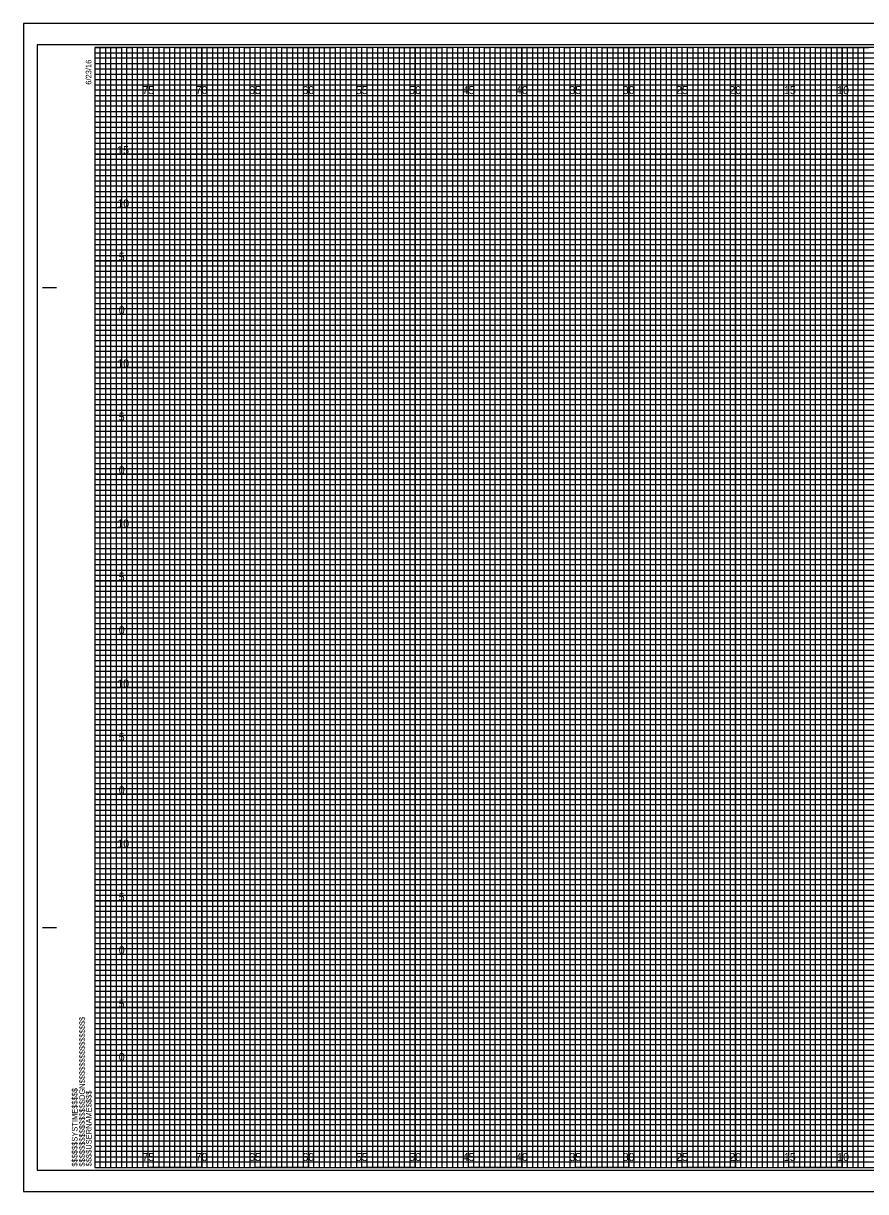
# Model space of a CAD drawing. Extents: x -7 to 162, y -2 to 107.
# Drawn here: x -6.7 to 72.2, y -2.3 to 107.3 of the extents above; entities that cross this region are included whole.
import ezdxf

# ---------------------------------------------------------------- set-up
doc = ezdxf.new("R2010")
doc.units = 0
for name, color, linetype in [('Prop XS Elevation Labels', 7, 'Continuous'), ('Prop XS Offset Labels', 7, 'Continuous'), ('Sheet Cross Section CELL', 7, 'Continuous'), ('Sheet Cross Section Grid Major CELL', 7, 'Continuous'), ('Sheet Cross Section Grid Middle CELL', 7, 'Continuous'), ('Sheet Cross Section Grid Minor 1 CELL', 7, 'Continuous'), ('Sheet Cross Section Grid Minor 2 CELL', 7, 'Continuous'), ('Sheet Cutting Line CELL', 7, 'Continuous'), ('Sheet DOT Grid CELL', 7, 'Continuous'), ('Sheet Plot Border Inside CELL', 7, 'Continuous'), ('Sheet Plot Border Outside CELL', 7, 'Continuous')]:
    doc.layers.add(name, color=color, linetype=linetype)

msp = doc.modelspace()

# ---------------------------------------------------------------- linework, layer by layer
at = {"layer": 'Sheet Cross Section CELL'}
for p, q in [((-4.9, 82.5), (-3.65, 82.5)), ((-4.85, 82.5), (-3.6, 82.5)), ((-4.9, 22.5), (-3.65, 22.5)), ((-4.85, 22.5), (-3.6, 22.5)), ((0, 0), (0, 0)), ((0, 0), (0, 0)), ((0, 0), (0, 0)), ((0, 0), (0, 0)), ((0, 0), (0, 0)), ((0, 0), (0, 0)), ((0, 0), (0, 0))]:
    msp.add_line(p, q, dxfattribs=at)
msp.add_lwpolyline([(160, 105), (0, 105), (0, 0), (160, 0)], close=True, dxfattribs=at)
at = {"layer": 'Sheet Cross Section Grid Major CELL'}
for p, q in [((5, 105), (0, 105)), ((5, 0), (5, 105)), ((15, 105), (10, 105)), ((10, 105), (10, 0)), ((15, 0), (15, 105)), ((25, 105), (20, 105)), ((20, 105), (20, 0)), ((25, 0), (25, 105)), ((35, 105), (30, 105)), ((30, 105), (30, 0)), ((35, 0), (35, 105)), ((45, 105), (40, 105)), ((40, 105), (40, 0)), ((45, 0), (45, 105)), ((55, 105), (50, 105)), ((50, 105), (50, 0)), ((55, 0), (55, 105)), ((65, 105), (60, 105)), ((60, 105), (60, 0)), ((65, 0), (65, 105)), ((75, 105), (70, 105)), ((70, 105), (70, 0)), ((10, 0), (5, 0)), ((20, 0), (15, 0)), ((30, 0), (25, 0)), ((40, 0), (35, 0)), ((50, 0), (45, 0)), ((60, 0), (55, 0)), ((70, 0), (65, 0))]:
    msp.add_line(p, q, dxfattribs=at)
for points in [[(0, 100), (160, 100), (160, 95), (0, 95)], [(0, 90), (160, 90), (160, 85), (0, 85)], [(0, 80), (160, 80), (160, 75), (0, 75)], [(0, 70), (160, 70), (160, 65), (0, 65)], [(0, 60), (160, 60), (160, 55), (0, 55)], [(0, 50), (160, 50), (160, 45), (0, 45)], [(0, 40), (160, 40), (160, 35), (0, 35)], [(0, 30), (160, 30), (160, 25), (0, 25)], [(0, 20), (160, 20), (160, 15), (0, 15)], [(0, 10), (160, 10), (160, 5), (0, 5)]]:
    msp.add_lwpolyline(points, dxfattribs=at)
at = {"layer": 'Sheet Cross Section Grid Middle CELL'}
for points in [[(0, 105), (2.5, 105), (2.5, 0), (7.5, 0), (7.5, 105), (12.5, 105), (12.5, 0), (17.5, 0), (17.5, 105), (22.5, 105), (22.5, 0), (27.5, 0), (27.5, 105), (32.5, 105), (32.5, 0), (37.5, 0), (37.5, 105), (42.5, 105), (42.5, 0), (47.5, 0), (47.5, 105), (52.5, 105), (52.5, 0), (57.5, 0), (57.5, 105), (62.5, 105), (62.5, 0), (67.5, 0), (67.5, 105), (72.5, 105)], [(0, 102.5), (137.5, 102.5)], [(0, 92.5), (160, 92.5), (160, 97.5), (0, 97.5)], [(0, 82.5), (160, 82.5), (160, 87.5), (0, 87.5)], [(0, 72.5), (160, 72.5), (160, 77.5), (0, 77.5)], [(0, 62.5), (160, 62.5), (160, 67.5), (0, 67.5)], [(0, 52.5), (160, 52.5), (160, 57.5), (0, 57.5)], [(0, 42.5), (160, 42.5), (160, 47.5), (0, 47.5)], [(0, 32.5), (160, 32.5), (160, 37.5), (0, 37.5)], [(0, 22.5), (160, 22.5), (160, 27.5), (0, 27.5)], [(0, 12.5), (160, 12.5), (160, 17.5), (0, 17.5)], [(0, 2.5), (160, 2.5), (160, 7.5), (0, 7.5)]]:
    msp.add_lwpolyline(points, dxfattribs=at)
at = {"layer": 'Sheet Cross Section Grid Minor 1 CELL'}
for p, q in [((0, 104.5), (130, 104.5)), ((130, 103.99), (0, 103.99)), ((0, 103.99), (0, 103.5)), ((0, 103.5), (130, 103.5)), ((130, 102.95), (0, 102.95)), ((0, 102.95), (0, 102)), ((0, 102), (160, 102))]:
    msp.add_line(p, q, dxfattribs=at)
for points in [[(0, 101.5), (135, 101.5), (160, 101.5), (160, 101), (0, 101)], [(0, 100.5), (160, 100.5), (160, 99.5), (0, 99.5)], [(0, 99), (160, 99), (160, 98.5), (0, 98.49)], [(0, 98), (160, 98), (160, 97), (0, 97)], [(0, 96.5), (160, 96.5), (160, 96), (0, 96)], [(0, 95.5), (160, 95.5), (160, 94.5), (0, 94.5)], [(0, 94), (160, 94), (160, 93.5), (0, 93.5)], [(0, 93), (160, 93), (160, 92), (0, 92)], [(0, 91.5), (160, 91.5), (160, 91), (0, 91)], [(0, 90.5), (160, 90.5), (160, 89.5), (0, 89.5)], [(0, 89), (160, 89), (160, 88.5), (0, 88.5)], [(0, 88), (160, 88), (160, 86.98), (160, 86.5), (160, 86), (0, 86)], [(0, 87), (160, 87), (160, 86.5), (0, 86.5)], [(0, 85.5), (160, 85.5), (160, 84.5), (0, 84.52)], [(0, 84.52), (160, 84.5), (160, 84), (0, 84)], [(0, 83.5), (160, 83.5), (160, 83), (0, 83)], [(0, 82), (160, 82), (160, 81.5), (0, 81.5)], [(0, 81), (160, 81), (160, 80.5), (0, 80.5)], [(-0.04, 79.45), (160, 79.45), (160, 78.94), (-0.04, 78.94)], [(0, 78.5), (160, 78.5), (160, 78), (0, 78)], [(0, 77), (160, 77), (160, 76.5), (0, 76.5)], [(0, 76), (160, 76), (160, 75.5), (0, 75.5)], [(0, 74.5), (160, 74.5), (160, 74), (0, 74)], [(0, 73.5), (160, 73.5), (160, 73), (0, 73)], [(0, 72), (160, 72), (160, 71.5), (0, 71.5)], [(0, 71), (160, 71), (160, 70.5), (0, 70.5)], [(0, 69.5), (160, 69.5), (160, 68.99), (0, 69)], [(0, 68.5), (160, 68.5), (160, 68), (0, 68)], [(0, 67), (160, 67), (160, 66.5), (0, 66.5)], [(0, 66), (160, 66), (160, 65.5), (0, 65.5)], [(0, 64.5), (160, 64.5), (160, 64), (0, 64)], [(0, 63.5), (160, 63.5), (160, 63), (0, 63)], [(0, 62), (160, 62), (160, 61.5), (0, 61.5)], [(0, 61), (160, 61), (160, 60.5), (0, 60.5)], [(0, 59.5), (160, 59.5), (160, 59), (0, 59)], [(0, 58.5), (160.03, 58.45), (160, 58), (0, 58)], [(0, 57), (160, 57), (160, 56.5), (0, 56.5)], [(0, 56), (160, 56), (160, 55.5), (0, 55.5)], [(0, 54.5), (160, 54.5), (160, 54), (0, 54)], [(0, 53.5), (160, 53.5), (160, 53), (0, 53)], [(0, 52), (160, 52), (160, 51.5), (0, 51.5)], [(0, 51), (160, 51), (160, 50.5), (0, 50.5)], [(0, 49.5), (160, 49.5), (160, 49), (0, 49)], [(0, 48.5), (160, 48.5), (160, 48), (0, 48)], [(0, 47), (160, 47), (160, 46.5), (0, 46.5)], [(0, 46), (160, 46), (160, 45.5), (0, 45.5)], [(0, 44.5), (160, 44.5), (160, 44), (0, 44)], [(0, 43.5), (160, 43.5), (160, 43), (0, 43)], [(0, 42), (160, 42), (160, 41.5), (0, 41.5)], [(0, 41), (160, 41), (160, 40.5), (0, 40.5)], [(0, 39.5), (160, 39.5), (160, 38.99), (0, 39)], [(0, 38.5), (160, 38.5), (160, 38), (0, 38)], [(0, 37), (160, 37), (160, 36.5), (0, 36.5)], [(0, 36), (160, 36), (160, 35.5), (0, 35.5)], [(0, 34.5), (160, 34.5), (160, 34), (0, 34)], [(0, 33.5), (160, 33.5), (160, 33), (0, 33)], [(0, 32), (160, 32), (160, 31.5), (0, 31.5)], [(0, 31), (160, 31), (160, 30.5), (0, 30.5)], [(0, 29.5), (160, 29.5), (160, 29), (0, 29)], [(0, 28.5), (160.03, 28.46), (160, 28), (0, 28)], [(0, 27), (160, 27), (160, 26.5), (0, 26.5)], [(0, 26), (160, 26), (160, 25.5), (0, 25.5)], [(0, 24.5), (160, 24.5), (160, 24), (0, 24)], [(0, 23.5), (160, 23.5), (160, 23), (0, 23)], [(0, 22), (160, 22), (160, 21.5), (0, 21.5)], [(0, 21), (160, 21), (160, 20.5), (0, 20.5)], [(0, 19.5), (160, 19.5), (160, 19), (0, 19)], [(0, 18.5), (160, 18.5), (160, 18), (0, 18)], [(0, 17), (160, 17), (160, 16.5), (0, 16.5)], [(0, 16), (160, 16), (160, 15.5), (0, 15.5)], [(0, 14.5), (160, 14.5), (160, 14), (0, 14)], [(0, 13.5), (160, 13.5), (160, 13), (0, 13)], [(0, 12), (160, 12), (160, 11.5), (0, 11.5)], [(0, 11), (160, 11), (160, 10.5), (0, 10.5)], [(0, 9.5), (160, 9.5), (160, 9), (0, 9)], [(0, 8.5), (160, 8.5), (160, 8), (0, 8)], [(0, 7), (160, 7), (160, 6.5), (0, 6.5)], [(0, 6), (160, 6), (160, 5.5), (0, 5.5)], [(0, 4.5), (160, 4.5), (160, 4), (0, 4)], [(0, 3.5), (160, 3.5), (160, 3), (0, 3)], [(0, 2), (160, 2), (160, 1.5), (0, 1.5)], [(0, 1), (160, 1), (160, 0.5), (0, 0.5)]]:
    msp.add_lwpolyline(points, dxfattribs=at)
at = {"layer": 'Sheet Cross Section Grid Minor 2 CELL'}
for points in [[(0, 0), (0.5, 0), (0.5, 105), (1, 105), (1, 0)], [(1, 0), (1.5, 0), (1.5, 105), (2, 105), (2, 0)], [(2.5, 0), (3, 0), (3, 105), (3.5, 105), (3.5, 0)], [(3.5, 0), (4, 0), (4, 105), (4.5, 105), (4.5, 0)], [(5, 0), (5.5, 0), (5.5, 105), (6, 105), (6, 0)], [(6, 0), (6.5, 0), (6.5, 105), (7, 105), (7, 0)], [(7.5, 0), (8, 0), (8, 105), (8.5, 105), (8.5, 0)], [(8.5, 0), (9, 0), (9, 105), (9.5, 105), (9.5, 0)], [(10, 0), (10.5, 0), (10.5, 105), (11, 105), (11, 0)], [(11, 0), (11.5, 0), (11.5, 105), (12, 105), (12, 0)], [(12.5, 0), (13, 0), (13, 105), (13.5, 105), (13.5, 0)], [(13.5, 0), (14, 0), (14, 105), (14.5, 105), (14.5, 0)], [(15, 0), (15.5, 0), (15.5, 105), (16, 105), (16, 0)], [(16, 0), (16.5, 0), (16.5, 105), (17, 105), (17, 0)], [(17.5, 0), (18, 0), (18, 105), (18.5, 105), (18.5, 0)], [(18.5, 0), (19, 0), (19, 105), (19.5, 105), (19.5, 0)], [(20, 0), (20.5, 0), (20.5, 105), (21, 105), (21, 0)], [(21, 0), (21.5, 0), (21.5, 105), (22, 105), (22, 0)], [(22.5, 0), (23, 0), (23, 105), (23.5, 105), (23.5, 0)], [(23.5, 0), (24, 0), (24, 105), (24.5, 105), (24.5, 0)], [(25, 0), (25.5, 0), (25.5, 105), (26, 105), (26, 0)], [(26, 0), (26.5, 0), (26.5, 105), (27, 105), (27, 0)], [(27.5, 0), (28, 0), (28, 105), (28.5, 105), (28.5, 0)], [(28.5, 0), (29, 0), (29, 105), (29.5, 105), (29.5, 0)], [(30, 0), (30.5, 0), (30.5, 105), (31, 105), (31, 0)], [(31, 0), (31.5, 0), (31.5, 105), (32, 105), (32, 0)], [(32.5, 0), (33, 0), (33, 105), (33.5, 105), (33.5, 0)], [(33.5, 0), (34, 0), (34, 105), (34.5, 105), (34.5, 0)], [(35, 0), (35.5, 0), (35.5, 105), (36, 105), (36, 0)], [(36, 0), (36.5, 0), (36.5, 105), (37, 105), (37, 0)], [(37.5, 0), (38, 0), (38, 105), (38.5, 105), (38.5, 0)], [(38.5, 0), (39, 0), (39, 105), (39.5, 105), (39.5, 0)], [(40, 0), (40.5, 0), (40.5, 105), (41, 105), (41, 0)], [(41, 0), (41.5, 0), (41.5, 105), (42, 105), (42, 0)], [(42.5, 0), (43, 0), (43, 105), (43.5, 105), (43.5, 0)], [(43.5, 0), (44, 0), (44, 105), (44.5, 105), (44.5, 0)], [(45, 0), (45.5, 0), (45.5, 105), (46, 105), (46, 0)], [(46, 0), (46.5, 0), (46.5, 105), (47, 105), (47, 0)], [(47.5, 0), (48, 0), (48, 105), (48.5, 105), (48.5, 0)], [(48.5, 0), (49, 0), (49, 105), (49.5, 105), (49.5, 0)], [(50, 0), (50.5, 0), (50.5, 105), (51, 105), (51, 0)], [(51, 0), (51.5, 0), (51.5, 105), (52, 105), (52, 0)], [(52.5, 0), (53, 0), (53, 105), (53.5, 105), (53.5, 0)], [(53.5, 0), (54, 0), (54, 105), (54.5, 105), (54.5, 0)], [(55, 0), (55.5, 0), (55.5, 105), (56, 105), (56, 0)], [(56, 0), (56.5, 0), (56.5, 105), (57, 105), (57, 0)], [(57.5, 0), (58, 0), (58, 105), (58.5, 105), (58.5, 0)], [(58.5, 0), (59, 0), (59, 105), (59.5, 105), (59.5, 0)], [(60, 0), (60.5, 0), (60.5, 105), (61, 105), (61, 0)], [(61, 0), (61.5, 0), (61.5, 105), (62, 105), (62, 0)], [(62.5, 0), (63, 0), (63, 105), (63.5, 105), (63.5, 0)], [(63.5, 0), (64, 0), (64, 105), (64.5, 105), (64.5, 0)], [(65, 0), (65.5, 0), (65.5, 105), (66, 105), (66, 0)], [(66, 0), (66.5, 0), (66.5, 105), (67, 105), (67, 0)], [(67.5, 0), (68, 0), (68, 105), (68.5, 105), (68.5, 0)], [(68.5, 0), (69, 0), (69, 105), (69.5, 105), (69.5, 0)], [(70, 0), (70.5, 0), (70.5, 105), (71, 105), (71, 0)], [(71, 0), (71.5, 0), (71.5, 105), (72, 105), (72, 0)]]:
    msp.add_lwpolyline(points, dxfattribs=at)
at = {"layer": 'Sheet Cutting Line CELL'}
for p, q in [((161.65, 107.25), (-6.7, 107.25)), ((-6.7, 107.25), (-6.7, -2.25)), ((-6.7, -2.25), (161.65, -2.25))]:
    msp.add_line(p, q, dxfattribs=at)
at = {"layer": 'Sheet DOT Grid CELL'}
for p, q in [((5, 0), (5, 105)), ((10, 0), (10, 105)), ((15, 0), (15, 105)), ((20, 0), (20, 105)), ((25, 0), (25, 105)), ((30, 0), (30, 105)), ((35, 0), (35, 105)), ((40, 0), (40, 105)), ((45, 0), (45, 105)), ((50, 0), (50, 105)), ((55, 0), (55, 105)), ((60, 0), (60, 105)), ((65, 0), (65, 105)), ((70, 0), (70, 105)), ((0, 100), (160, 100)), ((0, 95), (160, 95)), ((0, 90), (160, 90)), ((0, 85), (160, 85)), ((0, 80), (160, 80)), ((0, 75), (160, 75)), ((0, 70), (160, 70)), ((0, 65), (160, 65)), ((0, 60), (160, 60)), ((0, 55), (160, 55)), ((0, 50), (160, 50)), ((0, 45), (160, 45)), ((0, 40), (160, 40)), ((0, 35), (160, 35)), ((0, 30), (160, 30)), ((0, 25), (160, 25)), ((0, 20), (160, 20)), ((0, 15), (160, 15)), ((0, 10), (160, 10)), ((0, 5), (160, 5))]:
    msp.add_line(p, q, dxfattribs=at)
at = {"layer": 'Sheet Plot Border Inside CELL'}
msp.add_lwpolyline([(-5.4, -0.25), (161.2, -0.25), (161.2, 105.25), (-5.4, 105.25)], close=True, dxfattribs=at)
at = {"layer": 'Sheet Plot Border Outside CELL'}
msp.add_lwpolyline([(-6.7, -2.25), (161.65, -2.25), (161.65, 107.25), (-6.7, 107.25)], close=True, dxfattribs=at)

# ---------------------------------------------------------------- texts
at = {"layer": 'Prop XS Elevation Labels'}
for s, p in [('15', (2.08, 95)), ('10', (2.09, 90)), ('5', (2.23, 85)), ('0', (2.23, 80)), ('10', (2.09, 75)), ('5', (2.23, 70)), ('0', (2.23, 65)), ('10', (2.09, 60)), ('5', (2.23, 55)), ('0', (2.23, 50)), ('10', (2.09, 45)), ('5', (2.23, 40)), ('0', (2.23, 35)), ('10', (2.09, 30)), ('5', (2.23, 25)), ('0', (2.23, 20)), ('5', (2.23, 15)), ('0', (2.23, 10))]:
    msp.add_text(s, height=0.75, dxfattribs=at).set_placement(p)
at = {"layer": 'Prop XS Offset Labels'}
for s, p in [('75', (4.44, 100.62)), ('70', (9.43, 100.62)), ('65', (14.44, 100.62)), ('60', (19.43, 100.62)), ('55', (24.44, 100.62)), ('50', (29.43, 100.62)), ('45', (34.44, 100.62)), ('40', (39.43, 100.62)), ('35', (44.44, 100.62)), ('30', (49.43, 100.62)), ('25', (54.44, 100.62)), ('20', (59.43, 100.62)), ('15', (64.53, 100.62)), ('10', (69.52, 100.62)), ('75', (4.44, 0.62)), ('70', (9.43, 0.62)), ('65', (14.44, 0.62)), ('60', (19.43, 0.62)), ('55', (24.44, 0.62)), ('50', (29.43, 0.62)), ('45', (34.44, 0.62)), ('40', (39.43, 0.62)), ('35', (44.44, 0.62)), ('30', (49.43, 0.62)), ('25', (54.44, 0.62)), ('20', (59.43, 0.62)), ('15', (64.53, 0.62)), ('10', (69.52, 0.62))]:
    msp.add_text(s, height=0.75, dxfattribs=at).set_placement(p)
at = {"layer": 'Sheet Cross Section CELL'}
for s, p in [('6/23/16', (-0.33, 101.5)), ('$$$$$$$$$$$$$$$$DGN$$$$$$$$$$$$$$$$', (-0.94, 0.09)), ('$$$$$$SYSTIME$$$$$', (-1.63, 0.09)), ('$$$$USERNAME$$$$', (-0.31, 0.12))]:
    msp.add_text(s, height=0.525, rotation=90, dxfattribs=at).set_placement(p)

doc.saveas('drawing.dxf')
